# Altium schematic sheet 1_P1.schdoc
size 307 x 218 mm; Symbol: Drawing-Symbol_A4; Device: Drawing-Symbol_A4; @Project Name: Temp_Con_V116; @Page Count: 1; @Update Date: 2025-01-28; @Create Date: 2025-01-22; @Schematic Name: TEMP_PWR; @Page No: 1; @Page Name: P1; Company: EasyEDA.com; Version: V1.0; Page Size: A4; @Create Time: 19:54:10; @Update Time: 00:40:01; Width: 1170; Height: 825; Region Start: 1; X Region Count: 6; Y Region Count: 4; Blade Width: 10; Title Block Position: 3; @Board Name: TEMP_PWR
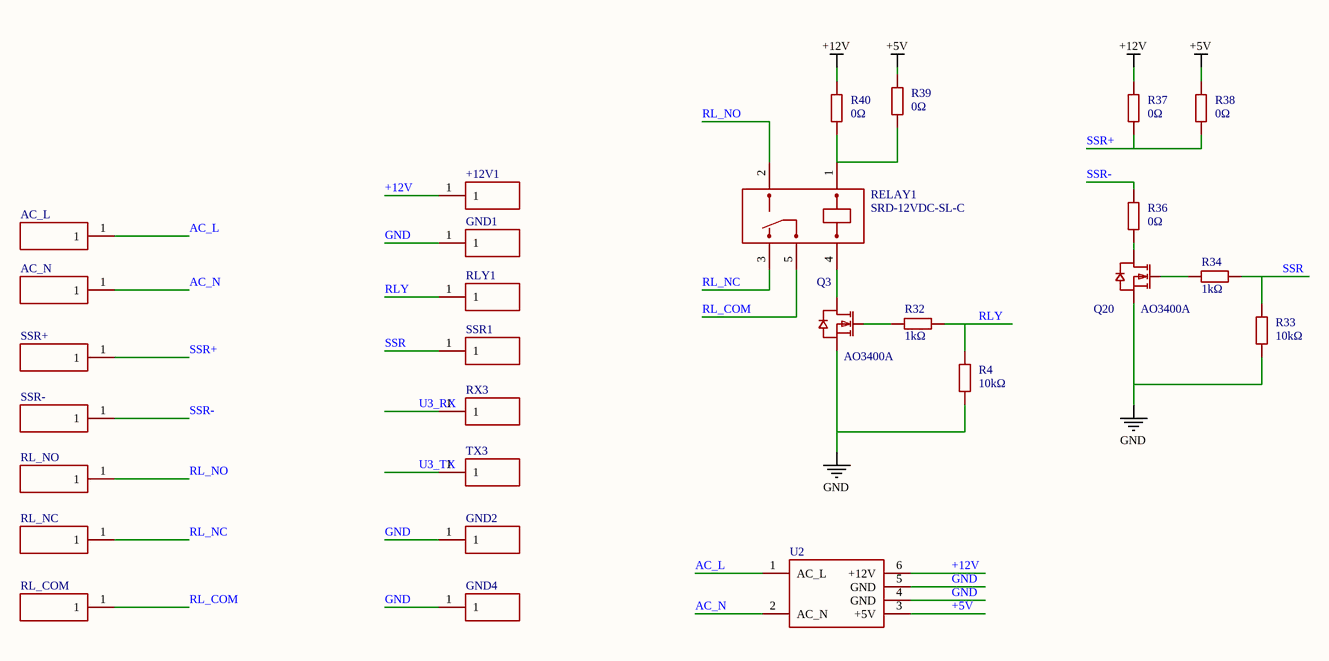
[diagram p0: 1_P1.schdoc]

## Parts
+12V1  (no value)  [S_FT]
AC_L  (no value)  [B_FT]
AC_N  (no value)  [B_FT]
GND1  (no value)  [S_FT]
GND2  (no value)  [S_FT]
GND4  (no value)  [S_FT]
Q3  AO3400A  [SOT-23-3_L2.9-W1.3-P1.90-LS2.4-BR]
Q20  AO3400A  [SOT-23-3_L2.9-W1.3-P1.90-LS2.4-BR]
R4  10kΩ  [R0805]
R32  1kΩ  [R0805]
R33  10kΩ  [R0805]
R34  1kΩ  [R0805]
R36  0Ω  [R0805]
R37  0Ω  [R0805]
R38  0Ω  [R0805]
R39  0Ω  [R0805]
R40  0Ω  [R0805]
RELAY1  SRD-12VDC-SL-C  [RELAY-TH_SRD-XXVDC-XL-C]
RL_COM  (no value)  [B_FT]
RL_NC  (no value)  [B_FT]
RL_NO  (no value)  [B_FT]
RLY1  (no value)  [S_FT]
RX3  (no value)  [S_FT]
SSR1  (no value)  [S_FT]
SSR+  (no value)  [B_FT]
SSR-  (no value)  [B_FT]
TX3  (no value)  [S_FT]
U2  (no value)  [P_MOD1]

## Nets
+5V: R38.2 R39.2 U2.3(+5V)
+12V: +12V1.1 R37.2 R40.2 U2.6(+12V)
GND: GND1.1 GND2.1 GND4.1 Q3.2(S) Q20.2(S) R4.1 R33.1 U2.4(GND) U2.5(GND)
AC_L: AC_L.1 U2.1(AC_L)
AC_N: AC_N.1 U2.2(AC_N)
RL_COM: RELAY1.5 RL_COM.1
RL_NC: RELAY1.3 RL_NC.1
RL_NO: RELAY1.2 RL_NO.1
RLY: R4.2 R32.2 RLY1.1
SSR: R33.2 R34.2 SSR1.1
SSR+: R37.1 R38.1 SSR+.1
SSR-: R36.2 SSR-.1
U3_RX: RX3.1
U3_TX: TX3.1
NetQ3_1: Q3.1(G) R32.1
NetQ3_3: Q3.3(D) RELAY1.4
NetQ20_1: Q20.1(G) R34.1
NetQ20_3: Q20.3(D) R36.1
NetR39_1: R39.1 R40.1 RELAY1.1

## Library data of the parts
+12V1 GND1 GND2 GND4 RLY1 RX3 SSR1 TX3 = S_TM: Add into BOM: no
AC_L AC_N RL_COM RL_NC RL_NO SSR+ SSR- = B_TM: Add into BOM: no
Q3 Q20 = AO3400A_C347475: Manufacturer: UMW(友台半导体); Add into BOM: yes; Type: 1 N-Channel; Drain Source On Resistance (RDS(on)@Vgs,Id): 28mΩ@10V,5.8A; Gate Threshold Voltage (Vgs(th)@Id): 1.4V@250uA; Total Gate Charge (Qg@Vgs): 12nC@10V; Input Capacitance (Ciss@Vds): 1050pF@24V; Reverse Transfer Capacitance (Crss@Vds): 77pF@15V; Check: true
R4 R33 = RC0805FR-0710KL: Manufacturer: YAGEO(国巨); Add into BOM: yes; Tolerance: ±1%; Temperature Coefficient: ±100ppm/℃; Check: true
R32 R34 = RC0805FR-071KL: Manufacturer: YAGEO(国巨); Add into BOM: yes; Tolerance: ±1%; Temperature Coefficient: ±100ppm/℃; Check: true
R36 R37 R40 = RC0805JR-070RL: Manufacturer: YAGEO(国巨); Add into BOM: yes; Tolerance: ±5%; Check: true
R38 R39 = RC0805JR-070RL: Manufacturer: YAGEO(国巨); Add into BOM: no; Convert to PCB: yes; Tolerance: ±5%; Check: true
RELAY1 = SRD-12VDC-SL-C: Manufacturer: 松乐; Add into BOM: yes; Coil Voltage: 12V; Contact Form: One Conversion: 1C (SPDT-Conversion); Pin Number: 5; Maximum Switching Voltage: 250V@AC; Coil Rated Power: 360mW; Maximum Switching Current: 15A; Coil Type: Non-polar - Single Coil; Coil Resistance: 400Ω; Contact Resistance: 100mΩ; Operate Time: 10ms; Check: true
U2 = P_12V5V_MOD: Add into BOM: yes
